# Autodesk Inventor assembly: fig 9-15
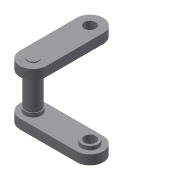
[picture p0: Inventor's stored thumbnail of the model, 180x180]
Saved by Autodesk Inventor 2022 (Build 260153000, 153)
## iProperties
Created: 2002-01
Part Number: fig 9-15
Document SubType Name: Assembly
Designer: ***
Control State: 0
Master: False
Checked Out: False
Shininess: 64.0
Length Units: 11269
Angle Units: 11279
Time Units: 11290
Mass Units: 11283
Length Display Precision: 3
Angle Display Precision: 2
Density: 0.0
Volumn: 0.0
Area: 0.0
PropertySet Name: Model Information
Author: ***
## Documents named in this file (3)
- D:\PROJECTS_2021\Resources\Part Files\c09_Inv_2022_prt\fig 9-15.iam
- D:\PROJECTS_2021\Resources\Part Files\c09_Inv_2022_prt\Part5.ipt
- D:\PROJECTS_2021\Resources\Part Files\c09_Inv_2022_prt\Part6.ipt
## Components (3 placed, 2 different names)
1. Part5:1 — Insert:1, Angle:1
2. Part6:1 — Insert:1, Insert:2
3. Part5:2 — Insert:2, Angle:1
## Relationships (3: Insert 2, Angle 1)
- Insert:1: Part5:1 ↔ Part6:1
- Insert:2: Part6:1 ↔ Part5:2
- Angle:1: Part5:1 ↔ Part5:2
